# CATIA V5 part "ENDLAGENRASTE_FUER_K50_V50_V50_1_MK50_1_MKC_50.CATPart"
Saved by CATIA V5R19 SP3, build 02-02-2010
Part number: ENDLAGENRASTE_FUER_K50_V50_V50_1_MK50_1_MKC_50
Bounding box of the stored display mesh (mm): x -108 to 64.916, y -68.024 to 18.597, z -43 to 43
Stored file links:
  G:\Konstruktion\Modelle\Catia_V5\Endlagenraste\ENDLAGENRASTE_FUER_K50_V50_V50_1_MK50_1_MKC_50.CATPart
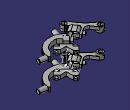
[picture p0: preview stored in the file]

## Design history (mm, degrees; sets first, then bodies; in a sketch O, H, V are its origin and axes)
AxisSystem1: origin (0, 0, 0), X (1, 0, 0), Y (0, 1, 0), Z (0, 0, 1)
Body1 "ENDLAGENRASTE_FUER_K50_V50_V50_1_MK50_1_MKC_50" (main body)
  Solid1 "Manifold Solid #290": solid without history
  Body2 "LUMP105"
    Solid2 "Manifold Solid #920": solid without history
  Assemble1: tool Body2
  Body3 "LUMP106"
    Solid3 "Manifold Solid #1329": solid without history
  Assemble2: tool Body3
  Body4 "LUMP107"
    Solid4 "Manifold Solid #1738": solid without history
  Assemble3: tool Body4
  Body5 "LUMP108"
    Solid5 "Manifold Solid #2147": solid without history
  Assemble4: tool Body5
  Body6 "LUMP109"
    Solid6 "Manifold Solid #2556": solid without history
  Assemble5: tool Body6
  Body7 "LUMP110"
    Solid7 "Manifold Solid #2941": solid without history
  Assemble6: tool Body7
  Body8 "LUMP111"
    Solid8 "Manifold Solid #3571": solid without history
  Assemble7: tool Body8
  Body9 "LUMP112"
    Solid9 "Manifold Solid #4879": solid without history
  Assemble8: tool Body9
  Body10 "LUMP113"
    Solid10 "Manifold Solid #6187": solid without history
  Assemble9: tool Body10
  Body11 "LUMP114"
    Solid11 "Manifold Solid #6444": solid without history
  Assemble10: tool Body11
  Body12 "LUMP115"
    Solid12 "Manifold Solid #6701": solid without history
  Assemble11: tool Body12
  Body13 "LUMP116"
    Solid13 "Manifold Solid #7411": solid without history
  Assemble12: tool Body13
  Body14 "LUMP117"
    Solid14 "Manifold Solid #8121": solid without history
  Assemble13: tool Body14
  Body15 "LUMP118"
    Solid15 "Manifold Solid #9264": solid without history
  Assemble14: tool Body15
  Body16 "LUMP119"
    Solid16 "Manifold Solid #10407": solid without history
  Assemble15: tool Body16
  Body17 "LUMP120"
    Solid17 "Manifold Solid #10792": solid without history
  Assemble16: tool Body17
  Body18 "LUMP121"
    Solid18 "Manifold Solid #11177": solid without history
  Assemble17: tool Body18
  Body19 "LUMP122"
    Solid19 "Manifold Solid #11586": solid without history
  Assemble18: tool Body19
  Body20 "LUMP123"
    Solid20 "Manifold Solid #11995": solid without history
  Assemble19: tool Body20
  Body21 "LUMP124"
    Solid21 "Manifold Solid #12404": solid without history
    Mirror1: of the body so far, about ZX plane of AxisSystem1
  Assemble20: tool Body21
  Body22 "LUMP125"
    Solid22 "Manifold Solid #12661": solid without history
  Assemble21: tool Body22
  Body23 "LUMP126"
    Solid23 "Manifold Solid #12918": solid without history
  Assemble22: tool Body23
  Body24 "LUMP127"
    Solid24 "Manifold Solid #13327": solid without history
  Assemble23: tool Body24
  Body25 "LUMP128"
    Solid25 "Manifold Solid #13736": solid without history
  Assemble24: tool Body25
  Body26 "LUMP129"
    Solid26 "Manifold Solid #13993": solid without history
  Assemble25: tool Body26
  Body27 "LUMP130"
    Solid27 "Manifold Solid #14250": solid without history
  Assemble26: tool Body27
  Body28 "LUMP131"
    Solid28 "Manifold Solid #14659": solid without history
  Assemble27: tool Body28
  Body29 "LUMP132"
    Solid29 "Manifold Solid #15068": solid without history
  Assemble28: tool Body29
  Body30 "LUMP133"
    Solid30 "Manifold Solid #15325": solid without history
  Assemble29: tool Body30
  Body31 "LUMP134"
    Solid31 "Manifold Solid #15582": solid without history
  Assemble30: tool Body31
  Body32 "LUMP135"
    Solid32 "Manifold Solid #15839": solid without history
  Assemble31: tool Body32
  Body33 "LUMP136"
    Solid33 "Manifold Solid #16096": solid without history
  Assemble32: tool Body33
  Rotate1: ToTransfor Assemble32, Angle 90, Axis edge [XY plane of AxisSystem1 | ZX plane of AxisSystem1]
